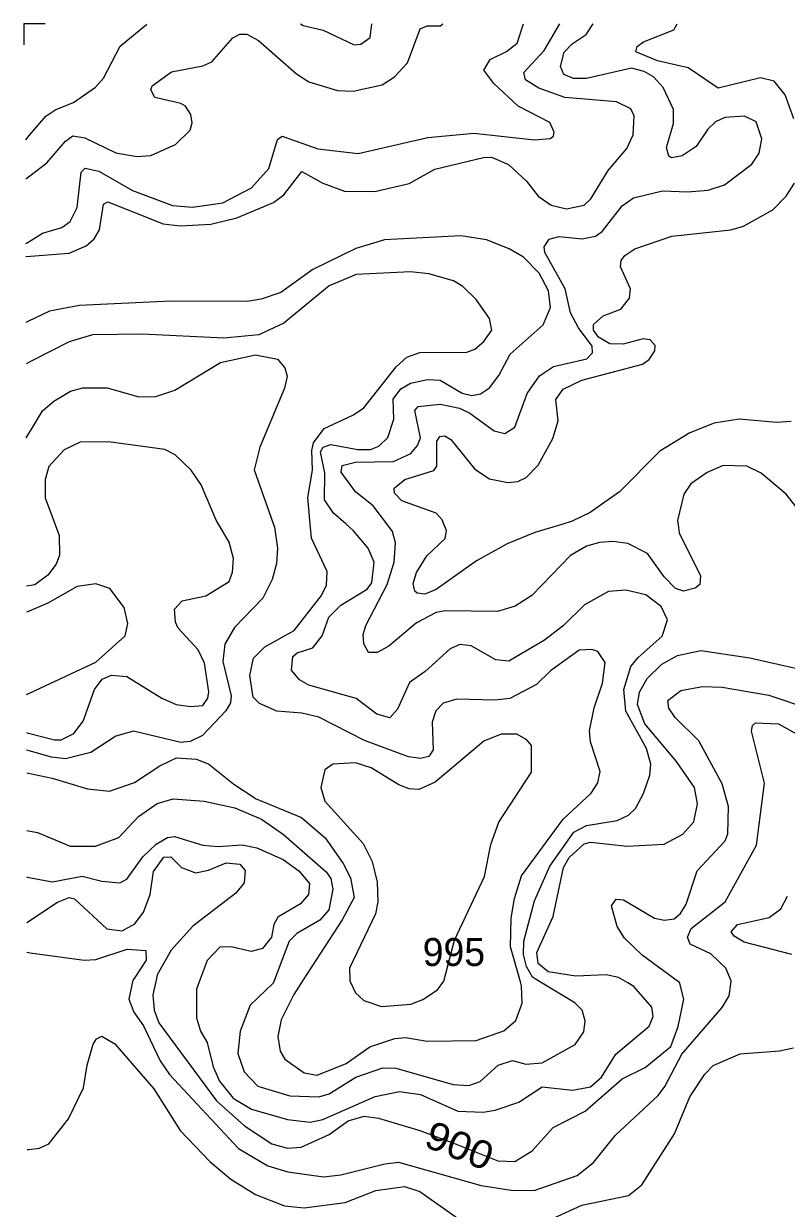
# Model space of a CAD drawing. Extents: x 473.9 to 500, y 7733.1 to 7760.8.
# Drawn here: x 473.884 to 476.066, y 7757.418 to 7760.807 of the extents above; entities that cross this region are included whole.
import ezdxf
from ezdxf.enums import TextEntityAlignment as Align

# ---------------------------------------------------------------- set-up
doc = ezdxf.new("R2010")
doc.units = 0
doc.header["$LTSCALE"] = 0.032
for name, color, linetype, lineweight in [('1', 7, 'Continuous', 25), ('2', 7, 'Continuous', 13), ('63', 7, 'Continuous', 13)]:
    doc.layers.add(name, color=color, linetype=linetype, lineweight=lineweight)
doc.layers.add('21', color=7, linetype='Continuous')
doc.layers.add('61', color=7, linetype='Continuous')

msp = doc.modelspace()

# ---------------------------------------------------------------- linework, layer by layer
at = {"layer": '1'}
for points in [[(473.8895, 7760.4743), (473.9007, 7760.4875), (473.9473, 7760.5423), (473.9758, 7760.5613), (474.0265, 7760.5812), (474.0891, 7760.625), (474.1119, 7760.6511), (474.1594, 7760.742), (474.2358, 7760.8056)], [(474.6757, 7760.8059), (474.6831, 7760.802), (474.7403, 7760.7885), (474.8291, 7760.7461), (474.8482, 7760.7483), (474.8753, 7760.7674), (474.8795, 7760.806)], [(476.0629, 7760.6034), (476.0309, 7760.6426), (475.9919, 7760.6514), (475.8711, 7760.6224), (475.7848, 7760.6804), (475.697, 7760.7007), (475.6352, 7760.7258), (475.6389, 7760.741), (475.6576, 7760.7547), (475.7438, 7760.7888), (475.7531, 7760.8067)], [(476.087, 7760.5348), (476.0629, 7760.6034)], [(476.0795, 7759.6685), (476.0388, 7759.6654), (475.9309, 7759.6757), (475.8593, 7759.6638), (475.7902, 7759.636), (475.7039, 7759.5833), (475.5885, 7759.4676), (475.505, 7759.4084), (475.4535, 7759.3831), (475.4231, 7759.3741), (475.3459, 7759.3511), (475.2671, 7759.319), (475.1792, 7759.2697), (475.0644, 7759.1881), (475.0317, 7759.1749), (475.0098, 7759.1771), (475.0027, 7759.1836), (474.9979, 7759.2052), (475.0077, 7759.2363), (475.037, 7759.2847), (475.0894, 7759.3343), (475.0934, 7759.3571), (475.0862, 7759.3751), (475.0814, 7759.3871), (475.0637, 7759.4065), (474.9653, 7759.4413), (474.9449, 7759.4632), (474.944, 7759.4782), (474.9743, 7759.5024), (475.0577, 7759.5286), (475.0654, 7759.5405), (475.0656, 7759.6124), (475.0745, 7759.6258), (475.0887, 7759.6277), (475.1061, 7759.617), (475.1749, 7759.5319), (475.217, 7759.5044), (475.2686, 7759.4941), (475.298, 7759.4972), (475.3218, 7759.5081), (475.3557, 7759.544), (475.398, 7759.6202), (475.4128, 7759.6705), (475.4059, 7759.7312), (475.4277, 7759.7613), (475.4809, 7759.7869), (475.654, 7759.8326), (475.6737, 7759.846), (475.69, 7759.8707), (475.6905, 7759.8862), (475.6764, 7759.9022), (475.6566, 7759.9047), (475.5987, 7759.8895), (475.5611, 7759.8911), (475.5285, 7759.9102), (475.5141, 7759.9295), (475.514, 7759.9466), (475.542, 7759.971), (475.5926, 7759.9899), (475.6167, 7760.0218), (475.62, 7760.0486), (475.5915, 7760.1114), (475.5934, 7760.1289), (475.6035, 7760.1438), (475.6326, 7760.1628), (475.7379, 7760.1988), (475.9068, 7760.2167), (475.9434, 7760.2274), (476.0276, 7760.2744), (476.0656, 7760.313), (476.0889, 7760.3504)], [(473.8921, 7758.7786), (473.8933, 7758.7783), (473.9717, 7758.7576), (473.991, 7758.7581), (474.0275, 7758.7761), (474.0539, 7758.811), (474.0865, 7758.9017), (474.1078, 7758.9317), (474.135, 7758.9426), (474.1784, 7758.9389), (474.2786, 7758.8775), (474.3199, 7758.8587), (474.3607, 7758.8533), (474.3967, 7758.8565), (474.4102, 7758.8771), (474.4135, 7758.8953), (474.4009, 7758.9775), (474.3827, 7759.0152), (474.3257, 7759.0772), (474.3177, 7759.095), (474.3148, 7759.1314), (474.3371, 7759.1554), (474.4052, 7759.1695), (474.4712, 7759.2112), (474.4816, 7759.2376), (474.4842, 7759.2771), (474.4719, 7759.3232), (474.4402, 7759.377), (474.4349, 7759.3861), (474.3914, 7759.4874), (474.3627, 7759.5294), (474.3172, 7759.5728), (474.2872, 7759.5881), (474.1268, 7759.6107), (474.0457, 7759.6092), (473.9999, 7759.5873), (473.9558, 7759.5402), (473.9447, 7759.5029), (473.9456, 7759.4501), (473.9719, 7759.3785), (473.9851, 7759.3425), (473.9865, 7759.2864), (473.9764, 7759.2606), (473.953, 7759.2291), (473.9152, 7759.2017), (473.8914, 7759.1976)], [(473.8929, 7758.235), (473.9806, 7758.2932), (474.0134, 7758.3065), (474.0293, 7758.3034), (474.1219, 7758.2169), (474.1656, 7758.2112), (474.2014, 7758.2313), (474.2268, 7758.2647), (474.246, 7758.3156), (474.2553, 7758.3811), (474.2845, 7758.4224), (474.3046, 7758.4232), (474.3349, 7758.3926), (474.3751, 7758.3773), (474.4122, 7758.3847), (474.4634, 7758.4059), (474.5019, 7758.4024), (474.5175, 7758.3837), (474.5149, 7758.3492), (474.4903, 7758.319), (474.3673, 7758.2251), (474.3053, 7758.1559), (474.2657, 7758.0852), (474.2634, 7758.0748), (474.2531, 7758.0283), (474.2573, 7757.9843), (474.2704, 7757.948), (474.4356, 7757.7248), (474.5153, 7757.6538), (474.5938, 7757.6025), (474.639, 7757.5897), (474.6773, 7757.5925), (474.7578, 7757.6292), (474.8121, 7757.6683), (474.858, 7757.6809), (474.899, 7757.676), (475.0176, 7757.6407), (475.1161, 7757.6031), (475.2404, 7757.5533), (475.289, 7757.5517), (475.3388, 7757.5822), (475.3988, 7757.6493), (475.4905, 7757.6958), (475.5959, 7757.7882), (475.662, 7757.8202), (475.7357, 7757.8806), (475.7567, 7757.9378), (475.7729, 7758.0157), (475.7611, 7758.0611), (475.7607, 7758.0625), (475.6529, 7758.1423), (475.6026, 7758.1908), (475.582, 7758.2242), (475.5656, 7758.2827), (475.5793, 7758.3019), (475.6003, 7758.3002), (475.6889, 7758.2481), (475.7177, 7758.2424), (475.7453, 7758.2458), (475.7629, 7758.2611), (475.7789, 7758.2877), (475.8111, 7758.3835), (475.8907, 7758.4693), (475.8987, 7758.4886), (475.9002, 7758.5673), (475.8818, 7758.6324), (475.8156, 7758.7552), (475.7477, 7758.8214), (475.7295, 7758.849), (475.7272, 7758.8708), (475.764, 7758.8992), (475.8262, 7758.9103), (475.8827, 7758.9089), (476.0155, 7758.8859), (476.1409, 7758.8442)]]:
    msp.add_lwpolyline(points, dxfattribs=at)
at = {"layer": '2'}
for points in [[(473.8897, 7760.3629), (473.9013, 7760.3716), (473.9503, 7760.4082), (474.0031, 7760.4707), (474.0239, 7760.4855), (474.0583, 7760.4799), (474.1476, 7760.4369), (474.2079, 7760.4268), (474.2475, 7760.4293), (474.3182, 7760.4609), (474.3598, 7760.5022), (474.366, 7760.5229), (474.3623, 7760.5472), (474.347, 7760.5703), (474.3332, 7760.5785), (474.2594, 7760.5954), (474.2475, 7760.6175), (474.2509, 7760.6292), (474.3066, 7760.6694), (474.3967, 7760.6864), (474.4225, 7760.6977), (474.4826, 7760.7661), (474.5022, 7760.7769), (474.5222, 7760.7769), (474.5552, 7760.7584), (474.6643, 7760.6631), (474.6996, 7760.6403), (474.7813, 7760.6156), (474.8264, 7760.6141), (474.9095, 7760.6318), (474.9445, 7760.6542), (474.9818, 7760.6944), (475.0179, 7760.7916), (475.0384, 7760.8001), (475.0765, 7760.8009), (475.0831, 7760.8062)], [(473.89, 7760.1405), (473.8904, 7760.1405), (474.0137, 7760.1506), (474.0622, 7760.1709), (474.085, 7760.1908), (474.1009, 7760.2174), (474.1124, 7760.2901), (474.1243, 7760.2969), (474.2829, 7760.2337), (474.3311, 7760.2281), (474.4195, 7760.2328), (474.4936, 7760.2511), (474.5981, 7760.2951), (474.6277, 7760.317), (474.6799, 7760.3839), (474.7396, 7760.35), (474.8021, 7760.3276), (474.8881, 7760.3271), (474.9866, 7760.3497), (475.0602, 7760.3902), (475.1989, 7760.4243), (475.2225, 7760.4244), (475.2708, 7760.4038), (475.3223, 7760.3564), (475.3562, 7760.3137), (475.3931, 7760.288), (475.4364, 7760.2771), (475.487, 7760.2877), (475.5061, 7760.3053), (475.5565, 7760.3868), (475.6098, 7760.4501), (475.6274, 7760.4887), (475.6309, 7760.5433), (475.6208, 7760.5632), (475.58, 7760.5827), (475.4321, 7760.5956), (475.3575, 7760.6218), (475.3196, 7760.6458), (475.3152, 7760.6667), (475.3734, 7760.7298), (475.4175, 7760.8065)], [(473.89, 7760.1777), (473.8932, 7760.1797), (473.9371, 7760.2074), (473.9927, 7760.2234), (474.017, 7760.2411), (474.0366, 7760.2806), (474.0478, 7760.3823), (474.0592, 7760.3938), (474.0991, 7760.3848), (474.1953, 7760.3295), (474.3097, 7760.2869), (474.3663, 7760.2822), (474.4533, 7760.2942), (474.5359, 7760.3375), (474.5855, 7760.3924), (474.6095, 7760.4757), (474.623, 7760.485), (474.7257, 7760.4486), (474.8412, 7760.4355), (475.0402, 7760.4812), (475.1716, 7760.4934), (475.3452, 7760.4742), (475.3899, 7760.4781), (475.3999, 7760.4845), (475.4014, 7760.4967), (475.3891, 7760.5241), (475.2987, 7760.5709), (475.2292, 7760.6353), (475.2001, 7760.6739), (475.2181, 7760.7047), (475.2648, 7760.7267), (475.296, 7760.7513), (475.3138, 7760.8064)], [(475.4568, 7760.6502), (475.4288, 7760.6613), (475.42, 7760.6838), (475.4297, 7760.7254), (475.453, 7760.749), (475.4932, 7760.7754), (475.5131, 7760.8065)], [(476.1347, 7759.3719), (476.0657, 7759.4609), (475.9936, 7759.5208), (475.9531, 7759.5411), (475.8849, 7759.5431), (475.8392, 7759.523), (475.7924, 7759.4901), (475.7728, 7759.4606), (475.7546, 7759.3851), (475.7564, 7759.3731), (475.7597, 7759.3506), (475.8204, 7759.2274), (475.818, 7759.2024), (475.8052, 7759.192), (475.7718, 7759.1837), (475.7491, 7759.1911), (475.7165, 7759.2239), (475.6684, 7759.2906), (475.6128, 7759.3194), (475.5699, 7759.3252), (475.5313, 7759.3227), (475.4938, 7759.3118), (475.4479, 7759.2854), (475.3372, 7759.1709), (475.2896, 7759.1399), (475.2395, 7759.1254), (475.0896, 7759.1274), (475.0639, 7759.1226), (475.0072, 7759.0925), (474.9282, 7759.0256), (474.8955, 7759.008), (474.8701, 7759.0077), (474.8567, 7759.0326), (474.8546, 7759.0596), (474.8623, 7759.0854), (474.9233, 7759.2027), (474.944, 7759.2666), (474.9472, 7759.3212), (474.9389, 7759.3538), (474.9226, 7759.3756), (474.8841, 7759.4269), (474.8328, 7759.4671), (474.7924, 7759.5233), (474.7948, 7759.5431), (474.8334, 7759.5519), (474.9422, 7759.5542), (474.9915, 7759.5769), (475.0109, 7759.6), (475.0187, 7759.622), (475.0029, 7759.7005), (475.0125, 7759.7114), (475.0751, 7759.7183), (475.1309, 7759.7065), (475.1603, 7759.6926), (475.2295, 7759.6421), (475.2603, 7759.6339), (475.2886, 7759.6521), (475.3244, 7759.7492), (475.3593, 7759.7992), (475.3994, 7759.8257), (475.495, 7759.8479), (475.5111, 7759.8647), (475.5103, 7759.8845), (475.4711, 7759.9366), (475.4487, 7759.9795), (475.4334, 7760.0483), (475.3749, 7760.1525), (475.3729, 7760.1687), (475.3874, 7760.1902), (475.4155, 7760.1976), (475.4815, 7760.1912), (475.5199, 7760.1988), (475.5391, 7760.2126), (475.5958, 7760.2856), (475.6283, 7760.3085), (475.7114, 7760.3286), (475.7829, 7760.3254), (475.8426, 7760.3309), (475.8887, 7760.3455), (475.9668, 7760.4051), (475.988, 7760.4366), (475.9957, 7760.4774), (475.9795, 7760.5259), (475.946, 7760.5421), (475.8903, 7760.5381), (475.8631, 7760.5264), (475.8413, 7760.5051), (475.8083, 7760.4549), (475.7682, 7760.4284), (475.7369, 7760.4228), (475.7294, 7760.4278), (475.7232, 7760.4527), (475.7434, 7760.5208), (475.7431, 7760.5616), (475.7139, 7760.6242), (475.6861, 7760.655), (475.6591, 7760.6704), (475.6224, 7760.6793), (475.4937, 7760.6501), (475.4568, 7760.6502)], [(474.7697, 7759.4066), (474.7448, 7759.4446), (474.7453, 7759.5205), (474.7325, 7759.5819), (474.7403, 7759.5952), (474.7621, 7759.6032), (474.8398, 7759.5889), (474.8763, 7759.5888), (474.9002, 7759.5983), (474.9257, 7759.6225), (474.9432, 7759.6749), (474.9409, 7759.7327), (474.9625, 7759.7618), (474.9905, 7759.7781), (475.0387, 7759.7892), (475.0756, 7759.7873), (475.1383, 7759.7494), (475.1663, 7759.7426), (475.1909, 7759.7475), (475.2166, 7759.7651), (475.2434, 7759.8003), (475.2754, 7759.8615), (475.3698, 7759.9456), (475.3911, 7759.995), (475.385, 7760.0422), (475.3582, 7760.0933), (475.3141, 7760.139), (475.2729, 7760.163), (475.2082, 7760.1884), (475.1348, 7760.1999), (474.9165, 7760.188), (474.834, 7760.1639), (474.7107, 7760.1036), (474.619, 7760.0379), (474.5632, 7760.0182), (474.5235, 7760.0119), (474.3044, 7760.0133), (474.0433, 7760.0004), (473.9576, 7759.9845), (473.8957, 7759.9548), (473.8903, 7759.9522)], [(474.8347, 7760.0889), (474.7576, 7760.0568), (474.6281, 7759.9501), (474.5568, 7759.9168), (474.4565, 7759.9073), (474.2229, 7759.9187), (474.0803, 7759.9162), (474.0139, 7759.8969), (473.907, 7759.8423), (473.8905, 7759.8339)], [(473.8923, 7758.6637), (473.9656, 7758.6482), (474.0659, 7758.6177), (474.1291, 7758.6113), (474.2009, 7758.6357), (474.2732, 7758.6831), (474.3206, 7758.7062), (474.3778, 7758.7027), (474.4131, 7758.6881), (474.4846, 7758.6309), (474.5488, 7758.589), (474.6786, 7758.5356), (474.7459, 7758.4774), (474.7975, 7758.4045), (474.8184, 7758.3633), (474.8289, 7758.3067), (474.7948, 7758.2427), (474.6838, 7758.071), (474.6568, 7758.0293), (474.6203, 7757.9565), (474.6113, 7757.9088), (474.6177, 7757.8676), (474.6309, 7757.844), (474.6865, 7757.8053), (474.7235, 7757.7987), (474.8066, 7757.8322), (474.8742, 7757.8796), (474.946, 7757.9035), (474.976, 7757.9061), (475.0381, 7757.8959), (475.178, 7757.8981), (475.2574, 7757.925), (475.2923, 7757.9551), (475.3098, 7758.0047), (475.3084, 7758.0537), (475.3051, 7758.0653), (475.2762, 7758.1656), (475.2786, 7758.2481), (475.2878, 7758.3037), (475.3081, 7758.3687), (475.4276, 7758.5314), (475.5077, 7758.6057), (475.5269, 7758.6346), (475.5334, 7758.6675), (475.5059, 7758.7525), (475.5029, 7758.7841), (475.516, 7758.8495), (475.5397, 7758.9203), (475.5479, 7758.9789), (475.5269, 7759.0108), (475.5093, 7759.0164), (475.4731, 7759.014), (475.3906, 7758.9556), (475.3509, 7758.916), (475.2745, 7758.8762), (475.2322, 7758.871), (475.1233, 7758.8741), (475.0841, 7758.8626), (475.0633, 7758.8407), (475.0529, 7758.8087), (475.0556, 7758.7297), (475.0434, 7758.7107), (475.0194, 7758.7042), (474.9845, 7758.7093), (474.8587, 7758.7556), (474.7283, 7758.8225), (474.6795, 7758.8339), (474.6078, 7758.8396), (474.5586, 7758.8618), (474.5406, 7758.8801), (474.5308, 7758.9423), (474.5414, 7758.9914), (474.574, 7759.0239), (474.6578, 7759.0704), (474.7362, 7759.1704), (474.7501, 7759.2001), (474.7525, 7759.2398), (474.7075, 7759.3351), (474.7036, 7759.3762), (474.6965, 7759.4514), (474.7099, 7759.5292), (474.7078, 7759.586), (474.7127, 7759.6079), (474.743, 7759.6487), (474.8276, 7759.6878), (474.8568, 7759.7078), (474.9499, 7759.8251), (474.9798, 7759.8524), (475.0173, 7759.8663), (475.1512, 7759.8669), (475.175, 7759.8759), (475.2006, 7759.8975), (475.223, 7759.9299), (475.2164, 7759.9633), (475.1788, 7760.0175), (475.1407, 7760.0548), (475.114, 7760.0715), (475.0431, 7760.0914), (474.9905, 7760.097), (474.8347, 7760.0889)], [(473.8908, 7759.6219), (473.9104, 7759.654), (473.9379, 7759.6991), (473.9704, 7759.727), (474.0179, 7759.7556), (474.0532, 7759.7649), (474.123, 7759.765), (474.2131, 7759.7391), (474.2616, 7759.7399), (474.3159, 7759.7578), (474.4467, 7759.8373), (474.5468, 7759.859), (474.6097, 7759.8468), (474.6313, 7759.8221), (474.6378, 7759.7979), (474.6301, 7759.7644), (474.5592, 7759.595), (474.5429, 7759.5307), (474.5973, 7759.3766), (474.601, 7759.3662), (474.6096, 7759.3067), (474.6074, 7759.2627), (474.5944, 7759.2169), (474.5675, 7759.1634), (474.4866, 7759.0795), (474.4592, 7759.0313), (474.4532, 7758.9817), (474.477, 7758.884), (474.4752, 7758.8638), (474.4623, 7758.8411), (474.3956, 7758.7708), (474.3601, 7758.7533), (474.333, 7758.7504), (474.1977, 7758.7825), (474.1473, 7758.7681), (474.0754, 7758.7217), (474.0031, 7758.704), (473.9634, 7758.7083), (473.8989, 7758.7263), (473.8922, 7758.7282)], [(473.8925, 7758.499), (473.9228, 7758.4933), (474.0168, 7758.4536), (474.0896, 7758.4542), (474.1558, 7758.4782), (474.2124, 7758.5388), (474.2654, 7758.5754), (474.3114, 7758.5887), (474.4004, 7758.5825), (474.4876, 7758.5635), (474.5637, 7758.5308), (474.6273, 7758.4874), (474.7489, 7758.3804), (474.7625, 7758.3614), (474.768, 7758.3304), (474.7569, 7758.272), (474.7309, 7758.2424), (474.6652, 7758.2036), (474.6437, 7758.1824), (474.6012, 7758.0717), (474.5972, 7758.0614), (474.5314, 7757.9987), (474.5027, 7757.9249), (474.4964, 7757.8606), (474.515, 7757.8078), (474.5536, 7757.7674), (474.6456, 7757.7395), (474.7283, 7757.7367), (474.7573, 7757.7448), (474.834, 7757.793), (474.9118, 7757.8194), (474.9481, 7757.8185), (475.1126, 7757.7718), (475.1571, 7757.7695), (475.1897, 7757.7802), (475.2412, 7757.8274), (475.2825, 7757.841), (475.3206, 7757.8298), (475.3672, 7757.8341), (475.4618, 7757.886), (475.4863, 7757.9229), (475.4901, 7757.9537), (475.4814, 7757.985), (475.461, 7758.0059), (475.3627, 7758.0648), (475.3393, 7758.0788), (475.3225, 7758.1091), (475.3135, 7758.1439), (475.3148, 7758.1822), (475.345, 7758.2975), (475.3887, 7758.3964), (475.4582, 7758.4941), (475.4942, 7758.5126), (475.5823, 7758.5267), (475.6141, 7758.5422), (475.6342, 7758.5611), (475.6576, 7758.6047), (475.675, 7758.6571), (475.6783, 7758.6883), (475.6656, 7758.7336), (475.6066, 7758.8404), (475.601, 7758.902), (475.6212, 7758.968), (475.6415, 7758.9935), (475.7108, 7759.0546), (475.726, 7759.1008), (475.7078, 7759.1397), (475.6643, 7759.1723), (475.6064, 7759.1861), (475.557, 7759.1819), (475.4883, 7759.1437), (475.4281, 7759.0849), (475.3738, 7759.0435), (475.2718, 7758.983), (475.2343, 7758.987), (475.1641, 7759.0267), (475.1312, 7759.0309), (475.1041, 7759.0181), (475.0325, 7758.953), (474.9873, 7758.9217), (474.9531, 7758.8458), (474.9318, 7758.8212), (474.8944, 7758.8318), (474.8347, 7758.8765), (474.6994, 7758.914), (474.6726, 7758.9298), (474.65, 7758.9574), (474.6538, 7758.9961), (474.6663, 7759.0069), (474.7106, 7759.0212), (474.7379, 7759.0554), (474.7571, 7759.1089), (474.7915, 7759.143), (474.8669, 7759.1886), (474.8795, 7759.2068), (474.8867, 7759.2659), (474.8691, 7759.3066), (474.8278, 7759.3561), (474.805, 7759.3759), (474.7697, 7759.4066)], [(473.8919, 7758.8874), (473.9027, 7758.8924), (474.0898, 7758.9798), (474.174, 7759.0559), (474.1819, 7759.0905), (474.1713, 7759.1368), (474.1298, 7759.1905), (474.0903, 7759.2045), (474.037, 7759.1965), (473.9531, 7759.1487), (473.8989, 7759.1259), (473.8916, 7759.1228)], [(473.8927, 7758.3656), (473.8941, 7758.3653), (473.9661, 7758.3515), (474.0514, 7758.3676), (474.1071, 7758.3532), (474.1588, 7758.3492), (474.1786, 7758.3597), (474.2249, 7758.4235), (474.2626, 7758.4598), (474.2952, 7758.4785), (474.315, 7758.4811), (474.396, 7758.4568), (474.4405, 7758.4528), (474.5091, 7758.4577), (474.5505, 7758.4493), (474.626, 7758.4153), (474.6706, 7758.3829), (474.7017, 7758.3472), (474.6985, 7758.3157), (474.6754, 7758.2889), (474.6105, 7758.2502), (474.5992, 7758.2293), (474.593, 7758.193), (474.5671, 7758.1605), (474.5343, 7758.1522), (474.4769, 7758.1658), (474.4451, 7758.1649), (474.4087, 7758.1264), (474.3888, 7758.0737), (474.3779, 7758.0449), (474.3784, 7757.9629), (474.3899, 7757.9248), (474.4085, 7757.892), (474.4263, 7757.8225), (474.4444, 7757.7813), (474.4829, 7757.7326), (474.5353, 7757.7018), (474.6383, 7757.6716), (474.7034, 7757.6642), (474.7401, 7757.6722), (474.8897, 7757.7379), (474.9593, 7757.7518), (475.0188, 7757.7429), (475.1262, 7757.6959), (475.1984, 7757.6931), (475.2327, 7757.698), (475.3008, 7757.7216), (475.3674, 7757.7652), (475.4541, 7757.7558), (475.5056, 7757.7653), (475.537, 7757.7932), (475.5781, 7757.8591), (475.6738, 7757.939), (475.6852, 7757.9665), (475.6813, 7757.9931), (475.6299, 7758.0524), (475.6124, 7758.0625), (475.586, 7758.0778), (475.55, 7758.0855), (475.4632, 7758.0815), (475.3848, 7758.0938), (475.3556, 7758.1185), (475.3519, 7758.1496), (475.3985, 7758.2524), (475.4279, 7758.3923), (475.4442, 7758.4215), (475.4874, 7758.4606), (475.5056, 7758.4655), (475.6106, 7758.4537), (475.7161, 7758.4596), (475.7695, 7758.4878), (475.8011, 7758.5236), (475.8116, 7758.5751), (475.8027, 7758.6218), (475.752, 7758.6964), (475.6614, 7758.8037), (475.6397, 7758.8587), (475.6456, 7758.8941), (475.6676, 7758.9338), (475.7094, 7758.9748), (475.7542, 7758.9991), (475.8212, 7759.0133), (475.9611, 7758.9923), (476.1718, 7758.9449)], [(473.893, 7758.1503), (473.9021, 7758.149), (474.0568, 7758.1273), (474.0902, 7758.1299), (474.18, 7758.1595), (474.2328, 7758.1552), (474.2346, 7758.1278), (474.1999, 7758.0754), (474.1964, 7758.0701), (474.1843, 7758.0157), (474.1988, 7757.9785), (474.2261, 7757.9399), (474.2743, 7757.8395), (474.3007, 7757.8007), (474.4982, 7757.5889), (474.5825, 7757.539), (474.6392, 7757.5222), (474.7418, 7757.5074), (474.7911, 7757.5131), (474.9171, 7757.5454), (474.9559, 7757.5499), (475.1926, 7757.4833), (475.2782, 7757.4697), (475.344, 7757.4686), (475.4675, 7757.5114), (475.5141, 7757.5492), (475.5769, 7757.6272), (475.6987, 7757.7406), (475.7182, 7757.7657), (475.767, 7757.8588), (475.8823, 7757.992), (475.9024, 7758.0252), (475.9069, 7758.0598), (475.9081, 7758.0689), (475.8924, 7758.1044), (475.8496, 7758.1458), (475.791, 7758.1731), (475.7828, 7758.1935), (475.7933, 7758.218), (475.8909, 7758.2948), (475.9802, 7758.4563), (476.003, 7758.6341), (475.9662, 7758.7829), (475.9693, 7758.799), (475.9773, 7758.8061), (476.0437, 7758.804), (476.1017, 7758.7716)], [(476.0818, 7758.1436), (475.9455, 7758.1794), (475.9166, 7758.1962), (475.9083, 7758.2087), (475.9258, 7758.2301), (476.0166, 7758.2494), (476.0499, 7758.2748), (476.0695, 7758.3108)], [(473.8939, 7757.5857), (473.8977, 7757.5861), (473.9286, 7757.5895), (473.9559, 7757.6019), (474.012, 7757.6738), (474.0553, 7757.7621), (474.0653, 7757.8273), (474.0826, 7757.8876), (474.0925, 7757.9028), (474.1072, 7757.9101), (474.1443, 7757.8881), (474.2565, 7757.7598), (474.3313, 7757.64), (474.4167, 7757.5515), (474.4762, 7757.5012), (474.5469, 7757.4576), (474.6302, 7757.4244), (474.6865, 7757.419), (474.8038, 7757.4343), (474.8912, 7757.4682), (474.9734, 7757.48), (475.0172, 7757.4662), (475.1751, 7757.3541)], [(475.3436, 7757.3633), (475.481, 7757.4266), (475.6146, 7757.4539), (475.6524, 7757.4848), (475.7459, 7757.6304), (475.7893, 7757.7365), (475.8322, 7757.8012), (475.8567, 7757.8265), (475.9338, 7757.8595), (476.0465, 7757.8679), (476.086, 7757.8771)]]:
    msp.add_lwpolyline(points, dxfattribs=at)
msp.add_lwpolyline([(475.1166, 7758.1851), (475.2019, 7758.3672), (475.2201, 7758.4586), (475.2436, 7758.5228), (475.3371, 7758.6652), (475.3365, 7758.7415), (475.3234, 7758.7575), (475.2945, 7758.7739), (475.2499, 7758.7743), (475.2006, 7758.7543), (475.061, 7758.6368), (475.0144, 7758.6158), (474.9867, 7758.6178), (474.9571, 7758.6294), (474.878, 7758.6777), (474.833, 7758.6926), (474.7687, 7758.6881), (474.7451, 7758.6725), (474.7343, 7758.6217), (474.7451, 7758.5823), (474.8551, 7758.4617), (474.8804, 7758.4094), (474.8949, 7758.3504), (474.8967, 7758.2943), (474.8902, 7758.2599), (474.8164, 7758.1044), (474.8167, 7758.0698), (474.8167, 7758.0687), (474.8331, 7758.0346), (474.8569, 7758.0121), (474.9074, 7757.9955), (474.9911, 7758.0018), (475.0259, 7758.0151), (475.068, 7758.0429), (475.086, 7758.0672), (475.086, 7758.0673)], close=True, dxfattribs=at)
at = {"layer": '63'}
msp.add_lwpolyline([(473.9453, 7760.8066), (473.8837, 7760.8066), (473.8837, 7760.7459)], dxfattribs=at)

# ---------------------------------------------------------------- texts
at = {"layer": '21'}
msp.add_text('995', height=0.08, dxfattribs=at).set_placement((475.0254, 7758.1109))
at = {"layer": '61', "width": 1.1}
msp.add_text('900', height=0.08, rotation=338.199, dxfattribs=at).set_placement((475.116, 7757.56), align=Align.CENTER)

doc.saveas('drawing.dxf')
